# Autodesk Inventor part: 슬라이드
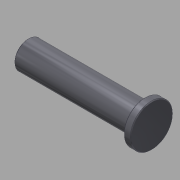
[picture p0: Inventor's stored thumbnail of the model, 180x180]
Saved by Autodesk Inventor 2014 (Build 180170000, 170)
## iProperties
Created: 2015-10
Part Number: 슬라이드
Document SubType Name: Modeling
Designer: mdu
Density: 7.86 g/cm^3
Material: 강철, 연강
Appearance: 강철 - 광택
Mass: 1603.27 g
Surface Area: 269.019 cm^2
Volume: 203.978 cm^3
Author: mdu
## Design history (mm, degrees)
sketch "스케치1"
  geometry: L1 (-75, 162)-(-75, 58) reference; L2 (-148, 110)-(22, 110); L3 (-148, 110)-(-148, 129); L4 (-148, 129)-(12, 129); L5 (12, 129)-(12, 139); L6 (12, 139)-(22, 139); L7 (22, 139)-(22, 110); 2 further points
  constraints: 12 end point, 3 parallel, 3 perpendicular, 1 midpoint, 1 point on line
  dimensions: "d0" = 58 diameter of L6 L2; "d1" = 38 diameter of L4 L2; "d2" = 10 distance of L5.end L6.end; "d3" = 170 distance of L2.start L2.end; "d4" = 73 distance between parallel lines of L3 L1
revolve "회전1" sketch "스케치1" stored, may be unused: angle "d5" = 90 deg
hole "구멍1" diameter "d11" = 13.376; stored, may be unused: countersink angle "d15" = 90 deg, drill point angle "d17" = 118 deg; dims "d9" = 10, "d10" = 10, "d12" = 22, "d13" = 4, "d14" = 2, "d16" = 25
chamfer "모따기1" distance "d6" = 1; stored, may be unused: second distance "d7" = 2, angle "d8" = 45 deg
node "솔리드1"
node "참조1"
